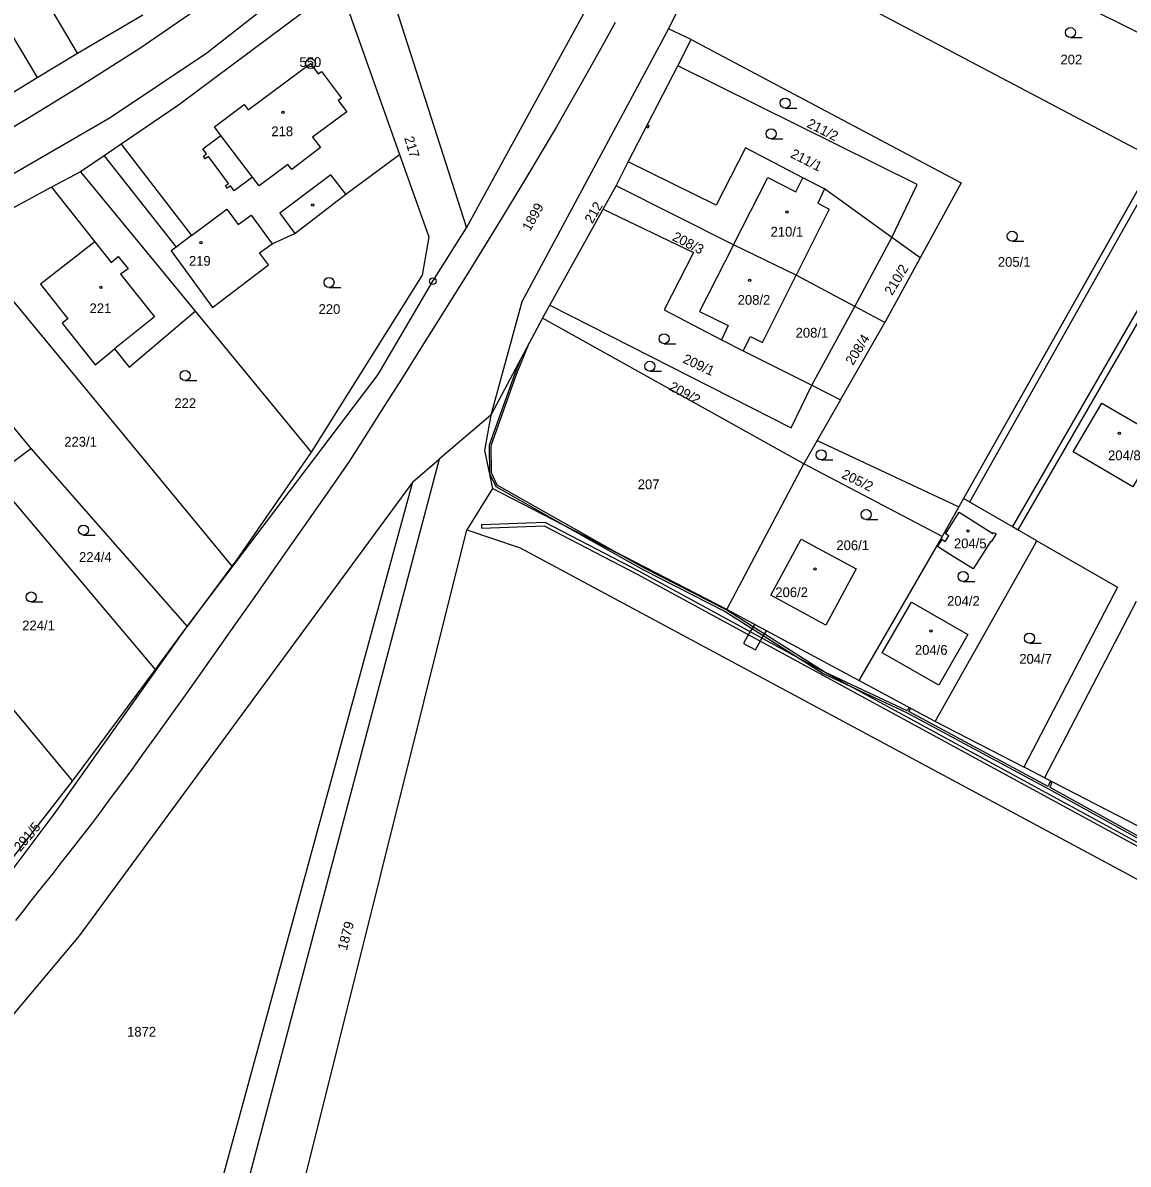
# Model space of a CAD drawing. Extents: x -587171 to -555306, y -1167727 to -1074732.
# Drawn here: x -560030 to -559864.5, y -1077700.6 to -1077529.7 of the extents above; entities that cross this region are included whole.
import ezdxf

# ---------------------------------------------------------------- set-up
doc = ezdxf.new("R2010")
doc.units = 0
for name, color, linetype in [('Hranice parcel', 7, 'Continuous'), ('Parcelní čísla', 7, 'Continuous'), ('Poz předměty', 7, 'Continuous'), ('Vnitřní kresba', 7, 'Continuous'), ('Věcná břemena k části', 7, 'Continuous'), ('Značky bodu BP', 7, 'Continuous'), ('Značky budov', 7, 'Continuous'), ('Značky kultur', 7, 'Continuous')]:
    doc.layers.add(name, color=color, linetype=linetype)

msp = doc.modelspace()

# ---------------------------------------------------------------- linework, layer by layer
at = {"layer": 'Hranice parcel'}
for p, q in [((-560021.8, -1077534.29), (-560041.8, -1077500.22)), ((-559919.16, -1077503.19), (-559825.2, -1077549.99)), ((-559933.32, -1077530.62), (-559925.65, -1077515.67)), ((-559925.65, -1077515.67), (-559860.44, -1077550.1)), ((-559977.02, -1077518.48), (-559963.57, -1077560.39)), ((-559982.58, -1077524.02), (-559973.58, -1077549.42)), ((-560021.8, -1077534.29), (-560012.02, -1077528.51)), ((-559929.9, -1077532.24), (-559933.32, -1077530.62)), ((-559931.92, -1077536.17), (-559929.9, -1077532.24)), ((-560027.82, -1077537.93), (-560021.8, -1077534.29)), ((-559939.32, -1077550.55), (-559931.92, -1077536.17)), ((-560036.72, -1077543.31), (-560027.82, -1077537.93)), ((-560015.24, -1077547.87), (-560017.82, -1077549.62)), ((-560017.82, -1077549.62), (-560021.33, -1077552.01)), ((-559860.44, -1077550.1), (-559889.12, -1077600.91)), ((-560021.33, -1077552.01), (-560025.67, -1077554.33)), ((-560021.33, -1077552.01), (-560004.18, -1077572.86)), ((-559941.15, -1077554.11), (-559939.32, -1077550.55)), ((-560025.67, -1077554.33), (-560039.43, -1077561.72)), ((-559943.09, -1077557.6), (-559941.15, -1077554.11)), ((-559923.55, -1077562.94), (-559941.15, -1077554.11)), ((-559951.09, -1077572), (-559943.09, -1077557.6)), ((-560039.43, -1077561.72), (-559998.7, -1077611.06)), ((-559905.39, -1077572.18), (-559899.89, -1077561.84)), ((-559895.63, -1077564.91), (-559899.89, -1077561.84)), ((-559914.18, -1077567.5), (-559923.55, -1077562.94)), ((-559895.63, -1077564.91), (-559900.9, -1077574.57)), ((-559905.39, -1077572.18), (-559914.18, -1077567.5)), ((-559952.15, -1077573.91), (-559951.09, -1077572)), ((-559911.83, -1077583.98), (-559905.39, -1077572.18)), ((-559900.9, -1077574.57), (-559905.39, -1077572.18)), ((-560004.18, -1077572.86), (-559986.81, -1077593.97)), ((-559952.15, -1077573.91), (-559959.91, -1077588.44)), ((-559913.04, -1077595.75), (-559952.15, -1077573.91)), ((-559907.53, -1077586.14), (-559900.9, -1077574.57)), ((-559925.39, -1077577.18), (-559922.1, -1077578.83)), ((-559922.1, -1077578.83), (-559911.83, -1077583.98)), ((-559911.83, -1077583.98), (-559907.53, -1077586.14)), ((-559907.53, -1077586.14), (-559911.02, -1077592.23)), ((-560034.25, -1077586.86), (-560028.8, -1077593.44)), ((-559959.91, -1077588.44), (-559967.63, -1077595.04)), ((-559911.02, -1077592.23), (-559913.04, -1077595.75)), ((-559911.02, -1077592.23), (-559889.82, -1077602.15)), ((-560032.92, -1077596.51), (-560028.8, -1077593.44)), ((-560028.8, -1077593.44), (-560005.37, -1077620.07)), ((-559971.59, -1077598.43), (-559967.63, -1077595.04)), ((-559924.58, -1077617.55), (-559913.04, -1077595.75)), ((-559892.35, -1077606.61), (-559913.04, -1077595.75)), ((-560010.14, -1077626.51), (-560034.06, -1077598.15)), ((-560000.39, -1077703.82), (-559971.59, -1077598.43)), ((-559959.64, -1077599.42), (-559963.5, -1077605.6)), ((-559924.58, -1077617.55), (-559959.64, -1077599.42)), ((-559889.12, -1077600.91), (-559889.82, -1077602.15)), ((-559878.13, -1077607.24), (-559889.12, -1077600.91)), ((-559889.82, -1077602.15), (-559892.35, -1077606.61)), ((-559892.35, -1077606.61), (-559904.81, -1077628.17)), ((-559878.13, -1077607.24), (-559866.08, -1077614.18)), ((-560049, -1077611.51), (-560022.53, -1077643.23)), ((-559998.7, -1077611.06), (-560005.37, -1077620.07)), ((-559866.08, -1077614.18), (-559880.09, -1077641.12)), ((-559863.26, -1077616.35), (-559876.99, -1077642.74)), ((-559904.81, -1077628.17), (-559924.58, -1077617.55)), ((-560010.14, -1077626.51), (-560005.37, -1077620.07)), ((-560022.53, -1077643.23), (-560010.14, -1077626.51)), ((-559893.37, -1077634.28), (-559904.81, -1077628.17)), ((-559880.09, -1077641.12), (-559893.37, -1077634.28)), ((-560037.66, -1077662.56), (-560022.53, -1077643.23))]:
    msp.add_line(p, q, dxfattribs=at)
for points in [[(-559963.57, -1077560.39), (-559941.07, -1077519.34), (-559927.71, -1077493.33)], [(-560041.8, -1077500.22), (-560049.33, -1077504.91), (-560054.91, -1077508.4), (-560049.65, -1077517.41), (-560045.84, -1077523.95), (-560045.24, -1077523.57), (-560040.92, -1077530.87), (-560034.4, -1077526.95), (-560027.82, -1077537.93)], [(-559982.58, -1077524.02), (-560006.65, -1077542.03), (-560015.24, -1077547.87)], [(-560038.88, -1077549.66), (-560028.99, -1077543.83), (-560021.74, -1077539.42), (-560012.48, -1077533.51), (-560002.56, -1077526.75)], [(-559933.32, -1077530.62), (-559955.28, -1077571.5), (-559959.91, -1077588.44)], [(-559929.9, -1077532.24), (-559889.5, -1077553.67), (-559895.63, -1077564.91)], [(-559899.89, -1077561.84), (-559896.05, -1077553.91), (-559931.92, -1077536.17)], [(-560015.24, -1077547.87), (-560004.71, -1077561.56), (-559999.44, -1077557.62), (-559997.72, -1077559.91), (-559995.81, -1077558.5), (-559992.64, -1077562.8)], [(-559899.89, -1077561.84), (-559909.96, -1077554.59), (-559913.21, -1077552.94), (-559921.78, -1077548.45), (-559926.16, -1077557.02), (-559939.32, -1077550.55)], [(-560017.82, -1077549.62), (-560007.04, -1077563.31), (-560007.76, -1077563.85), (-560001.58, -1077572.31), (-559993.21, -1077565.96), (-559994.54, -1077564.17), (-559992.64, -1077562.8)], [(-559992.64, -1077562.8), (-559989.26, -1077561.26), (-559981.62, -1077555.35), (-559973.58, -1077549.42)], [(-559973.58, -1077549.42), (-559969.19, -1077561.78), (-559970.17, -1077567.47), (-559986.81, -1077593.97)], [(-560025.67, -1077554.33), (-560019.21, -1077562.52), (-560027.33, -1077568.85), (-560023.26, -1077574.03), (-560024.1, -1077574.69), (-560019.15, -1077580.89), (-560017.25, -1077579.35), (-560016.24, -1077578.53), (-560014.04, -1077581.26), (-560004.18, -1077572.86)], [(-559943.09, -1077557.6), (-559929.57, -1077564.08), (-559933.95, -1077572.7), (-559925.39, -1077577.18)], [(-560005.37, -1077620.07), (-559976.78, -1077582.35), (-559968.6, -1077568.38), (-559963.57, -1077560.39)], [(-559923.55, -1077562.94), (-559928.64, -1077572.91), (-559924.35, -1077575.03), (-559925.39, -1077577.18)], [(-559922.1, -1077578.83), (-559921.05, -1077576.67), (-559919.21, -1077577.59), (-559914.18, -1077567.5)], [(-559951.09, -1077572), (-559914.94, -1077590.32), (-559911.83, -1077583.98)], [(-559859.51, -1077591.84), (-559863.76, -1077599.18), (-559872.72, -1077593.93), (-559868.43, -1077586.63), (-559859.51, -1077591.84)], [(-559959.91, -1077588.44), (-559960.86, -1077593.73), (-559959.64, -1077599.42)], [(-559986.81, -1077593.97), (-559998.05, -1077610.18), (-559998.7, -1077611.06)], [(-559967.63, -1077595.04), (-559997.55, -1077707.92), (-560083.3, -1078031.46)], [(-559971.59, -1077598.43), (-560021.55, -1077666.36), (-560049.7, -1077699.85), (-560071.03, -1077725.21)], [(-559885, -1077607.41), (-559885.1, -1077607.36), (-559886.09, -1077608.95), (-559887.71, -1077611.45), (-559891.09, -1077609.34), (-559893.03, -1077608.12), (-559892.34, -1077607.04), (-559891.86, -1077607.34), (-559891.34, -1077606.51), (-559891.82, -1077606.21), (-559889.78, -1077602.97), (-559884.74, -1077606.14), (-559884.64, -1077605.99), (-559884.25, -1077606.22), (-559885, -1077607.41)], [(-560009.36, -1077784.84), (-559989.19, -1077708.56), (-559963.5, -1077605.6)], [(-559963.5, -1077605.6), (-559955.52, -1077608.32), (-559848.35, -1077665.85)], [(-559917.96, -1077615.41), (-559913.46, -1077607.03), (-559905.23, -1077611.44), (-559909.74, -1077619.86), (-559917.96, -1077615.41)], [(-559893.37, -1077634.28), (-559878.82, -1077608.46), (-559878.13, -1077607.24)], [(-559901.29, -1077624.01), (-559896.94, -1077616.43), (-559888.47, -1077621.28), (-559892.82, -1077628.86), (-559901.29, -1077624.01)], [(-560036.86, -1077663.52), (-560025.28, -1077648.17), (-560005.37, -1077620.07)], [(-559825.82, -1077638.69), (-559837.39, -1077656.85), (-559849.04, -1077657.17), (-559876.99, -1077642.74)], [(-559876.99, -1077642.74), (-559879.65, -1077641.35), (-559880.09, -1077641.12)]]:
    msp.add_lwpolyline(points, dxfattribs=at)
at = {"layer": 'Poz předměty'}
for points in [[(-559941.3, -1077529.68), (-559942.93, -1077532.65), (-559944.62, -1077535.71), (-559946.36, -1077538.8), (-559948.17, -1077541.97), (-559950.08, -1077545.27), (-559952.06, -1077548.63), (-559954.13, -1077552.1), (-559956.32, -1077555.73), (-559958.56, -1077559.4), (-559960.87, -1077563.17), (-559963.27, -1077567.05), (-559965.71, -1077570.96), (-559968.19, -1077574.93), (-559970.74, -1077578.99), (-559973.29, -1077583.04), (-559975.87, -1077587.12), (-559978.5, -1077591.27), (-559981.1, -1077595.38)], [(-559981.1, -1077595.38), (-559983.97, -1077599.48), (-559986.86, -1077603.61), (-559989.7, -1077607.66), (-559992.49, -1077611.64), (-559995.26, -1077615.58), (-559997.93, -1077619.38), (-560000.52, -1077623.05), (-560003.04, -1077626.63), (-560005.43, -1077629.99), (-560007.7, -1077633.18), (-560009.85, -1077636.2), (-560011.84, -1077638.95), (-560013.67, -1077641.47), (-560015.37, -1077643.79), (-560016.93, -1077645.89), (-560018.37, -1077647.81), (-560019.72, -1077649.61), (-560020.98, -1077651.25), (-560022.17, -1077652.79), (-560023.32, -1077654.26), (-560024.42, -1077655.66), (-560025.5, -1077657.03), (-560026.59, -1077658.4), (-560027.67, -1077659.76), (-560028.78, -1077661.16), (-560029.93, -1077662.61), (-560031.09, -1077664.08)]]:
    msp.add_lwpolyline(points, dxfattribs=at)
at = {"layer": 'Vnitřní kresba'}
for p, q in [((-560002.41, -1077534.22), (-559985.42, -1077520.86)), ((-560016.91, -1077543.9), (-560002.41, -1077534.22)), ((-559996.24, -1077542.75), (-559986.89, -1077535.83)), ((-559986.89, -1077535.83), (-559985.74, -1077537.36)), ((-559985.74, -1077537.36), (-559985.25, -1077537.01)), ((-559985.25, -1077537.01), (-559982.27, -1077541)), ((-559982.27, -1077541), (-559982.74, -1077541.35)), ((-559982.74, -1077541.35), (-559981.46, -1077543.05)), ((-560001.3, -1077545.27), (-559996.83, -1077541.96)), ((-559996.83, -1077541.96), (-559996.24, -1077542.75)), ((-559981.46, -1077543.05), (-559986.6, -1077546.84)), ((-560034.88, -1077554.31), (-560016.91, -1077543.9)), ((-560000.31, -1077546.58), (-560001.3, -1077545.27)), ((-560003.02, -1077548.58), (-560000.31, -1077546.58)), ((-559995.6, -1077552.81), (-560000.31, -1077546.58)), ((-559986.6, -1077546.84), (-559985.41, -1077548.4)), ((-560002.48, -1077549.34), (-560003.02, -1077548.58)), ((-559985.41, -1077548.4), (-559989.7, -1077551.7)), ((-560002.94, -1077549.68), (-560002.48, -1077549.34)), ((-560002.68, -1077550.07), (-560002.94, -1077549.68)), ((-560002.2, -1077549.72), (-560002.68, -1077550.07)), ((-559999.17, -1077553.79), (-560002.2, -1077549.72)), ((-559990.29, -1077550.94), (-559994.61, -1077554.11)), ((-559989.7, -1077551.7), (-559990.29, -1077550.94)), ((-559999.65, -1077554.07), (-559999.17, -1077553.79)), ((-559995.6, -1077552.81), (-559998.32, -1077554.86)), ((-559994.61, -1077554.11), (-559995.6, -1077552.81)), ((-559983.87, -1077552.46), (-559991.5, -1077558.22)), ((-559981.62, -1077555.35), (-559983.87, -1077552.46)), ((-559923.55, -1077562.94), (-559918.42, -1077552.89)), ((-559918.42, -1077552.89), (-559914.26, -1077555.04)), ((-559914.26, -1077555.04), (-559913.21, -1077552.94)), ((-559999.38, -1077554.49), (-559999.65, -1077554.07)), ((-559998.87, -1077554.12), (-559999.38, -1077554.49)), ((-559998.32, -1077554.86), (-559998.87, -1077554.12)), ((-559909.96, -1077554.59), (-559910.95, -1077556.74)), ((-559910.95, -1077556.74), (-559909.26, -1077557.61)), ((-559991.5, -1077558.22), (-559989.26, -1077561.26)), ((-559909.26, -1077557.61), (-559914.18, -1077567.5)), ((-560004.71, -1077561.56), (-560007.04, -1077563.31)), ((-560019.21, -1077562.52), (-560016.76, -1077565.59)), ((-560016.76, -1077565.59), (-560015.7, -1077564.7)), ((-560015.7, -1077564.7), (-560014.22, -1077566.54)), ((-560014.22, -1077566.54), (-560015.35, -1077567.36)), ((-560015.35, -1077567.36), (-560010.28, -1077573.72)), ((-560010.28, -1077573.72), (-560016.24, -1077578.53))]:
    msp.add_line(p, q, dxfattribs=at)
at = {"layer": 'Věcná břemena k části'}
for points in [[(-559936.47, -1077545.01), (-559936.61, -1077545.28), (-559936.34, -1077545.44), (-559936.2, -1077545.17)], [(-559860.93, -1077553.08), (-559861.83, -1077552.57), (-559889.12, -1077600.91), (-559888.21, -1077601.44)], [(-559853.24, -1077557.69), (-559854.1, -1077557.19), (-559881.82, -1077605.12), (-559880.95, -1077605.62)], [(-559956.09, -1077582.48), (-559954.16, -1077577.68), (-559955.46, -1077580.1), (-559956.37, -1077582.37), (-559960.15, -1077592.94), (-559960.12, -1077597.17), (-559959.17, -1077599.14), (-559948.19, -1077605.34), (-559940.96, -1077609.08), (-559958.95, -1077598.92), (-559959.82, -1077597.1), (-559959.85, -1077592.99)], [(-559837.84, -1077665.91), (-559837.42, -1077665.56), (-559858.67, -1077654.81), (-559937.77, -1077611.78), (-559951.78, -1077604.49), (-559961.32, -1077604.87), (-559961.3, -1077605.37), (-559951.9, -1077604.99), (-559938.01, -1077612.22), (-559858.91, -1077655.25)], [(-559920.28, -1077623.58), (-559919.46, -1077622.1), (-559918.62, -1077620.75), (-559920.41, -1077619.79), (-559921.22, -1077621.06), (-559922.06, -1077622.6)]]:
    msp.add_lwpolyline(points, close=True, dxfattribs=at)
msp.add_lwpolyline([(-559848.1, -1077659.7), (-559876.17, -1077644.19), (-559875.93, -1077643.49), (-559876.2, -1077643.36), (-559876.44, -1077644.04), (-559897.32, -1077632.82), (-559897.03, -1077632.32), (-559897.3, -1077632.18), (-559897.59, -1077632.68), (-559909.99, -1077626.84), (-559924.68, -1077617.57), (-559936.92, -1077611.36), (-559940.96, -1077609.08), (-559948.19, -1077605.34), (-559937.06, -1077611.62), (-559924.83, -1077617.83), (-559910.14, -1077627.1), (-559897.59, -1077633.01), (-559876.42, -1077644.39), (-559848.17, -1077660)], dxfattribs=at)
at = {"layer": 'Značky bodu BP'}
for centre, radius in [((-559986.89, -1077535.83), 0.75), ((-559986.89, -1077535.83), 0.03), ((-559968.6, -1077568.38), 0.5), ((-559968.6, -1077568.38), 0.0303)]:
    msp.add_circle(centre, radius, dxfattribs=at)
at = {"layer": 'Značky budov'}
for centre in [(-559991.03, -1077543.12), (-559986.57, -1077556.99), (-559915.57, -1077558.02), (-560003.28, -1077562.64), (-560018.3, -1077569.31), (-559921.14, -1077568.28), (-559865.8, -1077591.19), (-559888.46, -1077605.76), (-559911.38, -1077611.46), (-559894.01, -1077620.75)]:
    msp.add_circle(centre, 0.175, dxfattribs=at)
at = {"layer": 'Značky kultur'}
for p, q in [((-559873.13, -1077531.94), (-559871.38, -1077531.94)), ((-559915.83, -1077542.49), (-559914.08, -1077542.49)), ((-559917.94, -1077547.09), (-559916.19, -1077547.09)), ((-559881.84, -1077562.42), (-559880.09, -1077562.42)), ((-559984.13, -1077569.34), (-559982.38, -1077569.34)), ((-559933.97, -1077577.75), (-559932.22, -1077577.75)), ((-559936.09, -1077581.88), (-559934.34, -1077581.88)), ((-560005.68, -1077583.26), (-560003.93, -1077583.26)), ((-559910.43, -1077595.13), (-559908.68, -1077595.13)), ((-559903.71, -1077604.08), (-559901.96, -1077604.08)), ((-560020.88, -1077606.39), (-560019.13, -1077606.39)), ((-559889.2, -1077613.34), (-559887.45, -1077613.34)), ((-560028.73, -1077616.41), (-560026.98, -1077616.41)), ((-559879.25, -1077622.57), (-559877.5, -1077622.57))]:
    msp.add_line(p, q, dxfattribs=at)
for centre in [(-559873.13, -1077531.19), (-559915.83, -1077541.74), (-559917.94, -1077546.34), (-559881.84, -1077561.67), (-559984.13, -1077568.59), (-559933.97, -1077577), (-559936.09, -1077581.13), (-560005.68, -1077582.51), (-559910.43, -1077594.38), (-559903.71, -1077603.33), (-560020.88, -1077605.64), (-559889.2, -1077612.59), (-560028.73, -1077615.66), (-559879.25, -1077621.82)]:
    msp.add_circle(centre, 0.75, dxfattribs=at)

# ---------------------------------------------------------------- texts
at = {"layer": 'Parcelní čísla'}
for s, p in [('202', (-559874.62, -1077535.95)), ('218', (-559992.77, -1077546.69)), ('210/1', (-559918.02, -1077561.72)), ('219', (-560005.11, -1077566.08)), ('205/1', (-559883.99, -1077566.24)), ('208/2', (-559922.95, -1077571.92)), ('221', (-560019.99, -1077573.18)), ('220', (-559985.7, -1077573.3)), ('208/1', (-559914.27, -1077576.84)), ('222', (-560007.29, -1077587.38)), ('223/1', (-560023.78, -1077593.16)), ('204/8', (-559867.49, -1077595.19)), ('207', (-559937.91, -1077599.53)), ('204/5', (-559890.57, -1077608.37)), ('206/1', (-559908.17, -1077608.65)), ('224/4', (-560021.56, -1077610.41)), ('206/2', (-559917.31, -1077615.68)), ('204/2', (-559891.59, -1077616.98)), ('224/1', (-560030.07, -1077620.65)), ('204/6', (-559896.41, -1077624.31)), ('204/7', (-559880.78, -1077625.65)), ('1872', (-560014.37, -1077681.46))]:
    msp.add_text(s, height=1.46, dxfattribs=at).set_placement(p)
for s, rotation, p in [('211/2', 333, (-559912.71, -1077545.26)), ('217', 287, (-559972.9, -1077546.96)), ('211/1', 333, (-559915.16, -1077549.8)), ('1899', 61, (-559954.03, -1077561.02)), ('212', 60, (-559944.71, -1077559.88)), ('208/3', 333, (-559932.85, -1077562.21)), ('210/2', 59, (-559899.83, -1077570.64)), ('208/4', 58, (-559905.69, -1077581.08)), ('209/1', 335, (-559931.29, -1077580.54)), ('209/2', 332, (-559933.34, -1077584.62)), ('205/2', 334, (-559907.51, -1077597.78)), ('291/5', 50, (-560030.35, -1077653.87)), ('1879', 75, (-559981.48, -1077668.66))]:
    msp.add_text(s, height=1.46, rotation=rotation, dxfattribs=at).set_placement(p)
at = {"layer": 'Značky bodu BP'}
msp.add_text('550', height=1.46, dxfattribs=at).set_placement((-559988.56, -1077536.33))

doc.saveas('drawing.dxf')
